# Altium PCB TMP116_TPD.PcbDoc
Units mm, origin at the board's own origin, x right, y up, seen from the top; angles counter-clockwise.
Board outline 10.92 x 3.99 mm, 2 copper layers (Top Layer, Bottom Layer), stack 0.605 mm thick; 19 components, 5 nets, 29 pads, 4 vias.
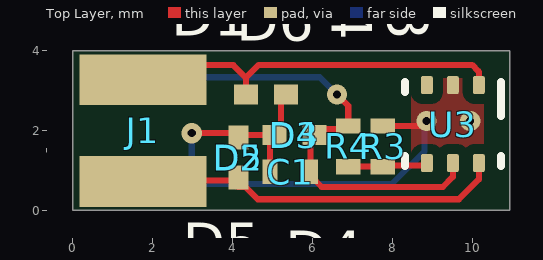
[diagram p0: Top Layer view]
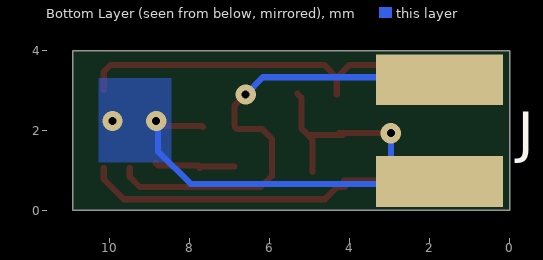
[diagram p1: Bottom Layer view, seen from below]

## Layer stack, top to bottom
Top Solder: solder mask 0.0102, Solder Resist, Dk 3.5
Top Layer: signal copper 0.0356
Dielectric1: core 0.5334, FR-4, Dk 4.2
Bottom Layer: signal copper 0.0356
Bottom Solder: solder mask 0.0102, Solder Resist, Dk 3.5

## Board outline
0,0 10.922,0 10.922,3.988 0,3.988

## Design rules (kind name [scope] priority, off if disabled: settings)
AcuteAngle [All] p1: minimum=4.50000000000000E+0001 checktracksonly=FALSE
AssemblyTestPointUsage [All] p1: valid=2
BoardOutlineClearance BoardOutlineClearance_MountingHoles [OnCopper and InComponentClass('Mounting Holes')] p1: gap=1.016 ignorepadtopadclearanceinfootprint=FALSE
BoardOutlineClearance BoardOutlineClearance_Poly [OnCopper and IsPoly] p2: gap=0.635 ignorepadtopadclearanceinfootprint=FALSE
BoardOutlineClearance [OnCopper and Not InComponentClass('Logo') and not InComponentClass('FiducialMark') and not InRegion(1000,500,4000,800) and not InPoly and not InComponent('J1','J2')] p3: gap=0.5 ignorepadtopadclearanceinfootprint=FALSE except(0.2: Track-OutlineEdge)
Clearance Clearance_2 [InNamedPolygon('BOTTOM_LAYER_GND_P002')] p1: gap=0.254 ignorepadtopadclearanceinfootprint=FALSE except(0: Arc-Hole Track-Hole SMDPad-Hole THPad-Hole Via-Via Via-Fill Via-Poly Via-Region Via-Text Via-Hole Fill-Hole Poly-Hole Region-Hole Text-Hole)
Clearance Clearance_1 [InNamedPolygon('TOP_LAYER_GND_P000')] p2: gap=0.254 ignorepadtopadclearanceinfootprint=FALSE except(0: Arc-Hole Track-Hole SMDPad-Hole THPad-Hole Via-Via Via-Fill Via-Poly Via-Region Via-Text Via-Hole Fill-Hole Poly-Hole Region-Hole Text-Hole)
Clearance Clearance_Keepouts [((IsTrack Or IsArc) And Not InPoly) And IsFree and IsKeepOut vs ((IsTrack Or IsArc) And Not InPoly) And IsFree and IsKeepOut] p3: gap=0 ignorepadtopadclearanceinfootprint=FALSE
Clearance Clearance_Poly [InPolygon] p4: gap=0.635 ignorepadtopadclearanceinfootprint=FALSE except(0: Arc-Hole Track-Hole SMDPad-Hole THPad-Hole Via-Hole Fill-Hole Poly-Hole Region-Hole Text-Hole)
Clearance Clearance_FiducialMark [IsKeepOut and InComponentClass('FiducialMark') vs IsPad and InComponentClass('FiducialMark')] p5: gap=0 ignorepadtopadclearanceinfootprint=FALSE
Clearance [All] p6: gap=0.2 ignorepadtopadclearanceinfootprint=FALSE except(0: Arc-Hole Track-Hole SMDPad-Hole THPad-Hole Via-Hole Fill-Hole Poly-Hole Region-Hole Text-Hole; 0.152: Arc-Arc Arc-Track Track-Track)
ComponentClearance ComponentClearance_AlternateParts [incomponent('D1') OR incomponent('D2') OR incomponent('D3') vs incomponent('U4') OR incomponent('U5') OR incomponent('U6')] p1: gap=0 collisioncheckmode=3 verticalgap=0 showdistances=FALSE
ComponentClearance ComponentClearance_MountingHoles_FiducialMarks [InComponentClass('Mounting Holes') vs InComponentClass('FiducialMark')] p2: gap=1.27 collisioncheckmode=3 verticalgap=0.254 showdistances=FALSE
ComponentClearance ComponentClearance_Shunt [InComponentClass('Header') vs InComponentClass('Shunt')] p3: gap=0 collisioncheckmode=3 verticalgap=0 showdistances=FALSE
ComponentClearance ComponentClearance_Logo [InComponentClass('Logo')] p4: gap=1.27 collisioncheckmode=3 verticalgap=0.254 showdistances=FALSE
ComponentClearance ComponentClearance_ScrewToNut [(HasFootprint('NY PMS 440 0025 PH')) vs (HasFootprint('Keystone_1902C'))] p5: gap=0.127 collisioncheckmode=3 verticalgap=0.254 showdistances=FALSE
ComponentClearance ComponentClearance_MountingHoles [InComponentClass('Mounting Holes')] p6: gap=6.35 collisioncheckmode=3 verticalgap=2540 showdistances=FALSE
ComponentClearance ComponentClearance_SmallPassives [HasFootprint('0201*') or HasFootprint('0402*') or HasFootprint('0508') or HasFootprint('0603*') or HasFootprint('0612') or HasFootprint('0805*') or HasFootprint('0815*') or HasFootprint('0830*') or HasFootprint('1206*') or HasFootprint('1210*') or HasFootprint('1808*') or HasFootprint('1812*') or HasFootprint('1825*') or HasFootprint('2010*') or HasFootprint('2220*') or HasFootprint('2225*') or HasFootprint('2512*') or HasFootprint('2728*') or HasFootprint('3518*') or HasFootprint('DPY0002A') vs HasFootprint('0201*') or HasFootprint('0402*') or HasFootprint('0508') or HasFootprint('0603*') or HasFootprint('0612') or HasFootprint('0805*') or HasFootprint('0815*') or HasFootprint('0830*') or HasFootprint('1206*') or HasFootprint('1210*') or HasFootprint('1808*') or HasFootprint('1812*') or HasFootprint('1825*') or HasFootprint('2010*') or HasFootprint('2220*') or HasFootprint('2225*') or HasFootprint('2512*') or HasFootprint('2728*') or HasFootprint('3518*') or HasFootprint('DPY0002A')] p7: gap=0.254 collisioncheckmode=3 verticalgap=0.254 showdistances=FALSE
ComponentClearance ComponentClearance_THtoSMT [IsThruComponent vs IsSMTComponent] p8: gap=1.016 collisioncheckmode=3 verticalgap=0.762 showdistances=FALSE
ComponentClearance ComponentClearance_THtoTH [IsThruComponent vs IsThruComponent] p9: gap=0.762 collisioncheckmode=3 verticalgap=0.762 showdistances=FALSE
ComponentClearance [All] p10: gap=0.381 collisioncheckmode=3 verticalgap=0.254 showdistances=FALSE
DiffPairsRouting [All] p1: maxlimit=2.54 minlimit=0.254 mostfreqgap=0.254 toplayer_minwidth=0.381 toplayer_maxwidth=0.381 toplayer_prefwidth=0.381 bottomlayer_minwidth=0.381 bottomlayer_maxwidth=0.381 bottomlayer_prefwidth=0.381 maxuncoupledlength=25.4
FabricationTestPointUsage TestPointUsage [All] p1: valid=2 allowmultiple=FALSE
FabricationTestpoint Testpoint [All] p1: side=3 testpointundercomponent=TRUE minsize=1.016 maxsize=2.54 preferedsize=1.524 minholesize=0 maxholesize=1.016 preferedholesize=0.813 testpointgrid=0.025 allowsidetop=TRUE allowsidebottom=TRUE usegrid=TRUE gridtolerance=0
FanoutControl Fanout_LCC [IsLCC] p1: bgadir=Out bgaviamode=Centered fanoutstyle=Auto fanoutdirection=Alternating viagrid=0.025 // Fanout_LCC (Default Rule)
FanoutControl Fanout_BGA [IsBGA] p2: bgadir=Out bgaviamode=Centered fanoutstyle=Auto fanoutdirection=Alternating viagrid=0.025 // Fanout_BGA (Default Rule)
FanoutControl Fanout_Default [All] p4: bgadir=Out bgaviamode=Centered fanoutstyle=Auto fanoutdirection=Alternating viagrid=0.025 // Fanout_Default (Default Rule)
FanoutControl Fanout_Small [(CompPinCount < 5)] p5: bgadir=Out bgaviamode=Centered fanoutstyle=Auto fanoutdirection=OutThenIn viagrid=0.025 // Fanout_Small (Default Rule)
HoleSize [All] p1: absolutevalues=TRUE maxlimit=6.375 minlimit=0.2 maxpercent=80.000 minpercent=20.000
MinimumAnnularRing MinimumAnnularRing_ThermalPadVias [IsVia and InAnyComponent] p1: minimumring=0.15
MinimumAnnularRing [All] p2: minimumring=0.152
MinimumSolderMaskSliver MinimumSolderMaskSliver_Logo [InComponentClass('Logo') vs InComponentClass('Logo')] p1: minsoldermaskwidth=0.018
MinimumSolderMaskSliver [All] p2: minsoldermaskwidth=0.1
PlaneConnect [All] p1: planeconnectstyle=Direct reliefexpansion=0.254 reliefentries=4 reliefconductorwidth=0.254 reliefairgap=0.254
PolygonConnect PolygonConnect_2 [All vs IsNamedPolygon('BOTTOM_LAYER_GND_P002')] p1: connectstyle=Direct reliefconductorwidth=0.254 reliefentries=4 polygonreliefangle="90 Angle" airgapwidth=0.254
PolygonConnect PolygonConnect_1 [All vs IsNamedPolygon('TOP_LAYER_GND_P000')] p2: connectstyle=Direct reliefconductorwidth=0.254 reliefentries=4 polygonreliefangle="90 Angle" airgapwidth=0.254
PolygonConnect [All] p3: thpad.connectstyle=Relief thpad.reliefconductorwidth=0.254 thpad.reliefentries=4 thpad.polygonreliefangle="90 Angle" thpad.airgapwidth=0.254 smdpad.connectstyle=Relief smdpad.reliefconductorwidth=0.254 smdpad.reliefentries=4 smdpad.polygonreliefangle="90 Angle" smdpad.airgapwidth=0.254 via.connectstyle=Direct via.reliefconductorwidth=0.254 via.reliefentries=4 via.polygonreliefangle="90 Angle" via.airgapwidth=0.254
RoutingVias ThermalPadVias [IsVia and InAnyComponent] p1: holewidth=0.2 width=0.5 viastyle="Through Hole" minholewidth=0.2 minwidth=0.5 maxholewidth=0.33 maxwidth=0.6
RoutingVias [All] p2: holewidth=0.406 width=0.864 viastyle="Through Hole" minholewidth=0.203 minwidth=0.508 maxholewidth=1.016 maxwidth=1.651
SilkToBoardRegionClearance [Not ((IsComment or IsDesignator) And (Hide <> 'False')) and not InRegion(1000,500,4000,800)] p1:
SilkToSilkClearance SilkToSilkClearance_Pb-FreeLogo [(HasFootprint('Pb-Free_Overlay_Medium') OR HasFootprint('Pb-Free_Overlay_Small')) vs (HasFootprint('Pb-Free_Overlay_Medium') OR HasFootprint('Pb-Free_Overlay_Small'))] p1: silktosilkclearance=0
SilkToSilkClearance [All] p2: silktosilkclearance=0.102
SilkToSolderMaskClearance SilkToComponentPadClearance [(IsPad or IsFill or IsRegion) and InAnycomponent] p1: minsilkscreentomaskgap=0.127 clearancetoexposedcopper=TRUE
SilkToSolderMaskClearance "Silk to Solder Mask Opening" [All] p2: minsilkscreentomaskgap=0.102 clearancetoexposedcopper=FALSE
SolderMaskExpansion [All] p1: expansion=0.05
Width [All] p1: maxlimit=2.54 minlimit=0.152 preferedwidth=0.254 checkconnectedcopper=TRUE
15 further rules are at their usual default settings.

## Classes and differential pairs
component class TMP116_TPD: C1 D1 D2 D3 D4 D5 D6 J1 J2 R3 R4 U3
component class EVM_Hardware: LBL1 Logo2 Logo3 ZZ1 ZZ2 ZZ3 ZZ4
component class AssemblyNote: ZZ1 ZZ2 ZZ3 ZZ4
component class Label: LBL1

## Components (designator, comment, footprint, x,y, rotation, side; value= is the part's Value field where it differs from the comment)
C1 "GCM155L81E104KE02J" 0402S 5.436,0.965 r180 top value=0.1uF
D1 "TPD1E04U04DPLR" DPY0002A 4.826,2.896 r0 top
D2 "TPD1E04U04DPLR" DPY0002A 4.14,1.321 r90 top
D3 "TPD1E04U04DPLR" DPY0002A 5.537,1.88 r180 top
D4 "ESD351DPYR" DPY0002A 5.537,1.88 r180 top
D5 "ESD351DPYR" DPY0002A 4.14,1.321 r90 top
D6 "ESD351DPYR" DPY0002A 4.826,2.896 r0 top
J1 "TSM-102-01-L-SH" Samtec_TSM-102-01-x-SH -3.527,1.994 r270 top
J2 "TSM-102-01-L-SH" Samtec_TSM-102-01-x-SH -3.527,1.994 r90 bottom
LBL1 "THT-14-423-10" Label_650x200 17.272,17.932 r0 top
Logo2 "Pb-Free Symbol" Pb-Free_Overlay_Small 5.817,14.656 r0 top
Logo3 "FCC disclaimer" FCC_disclaimer 8.357,23.622 r0 top
R3 "CRCW04020000Z0ED" 0402S 7.747,1.6 r90 top value=0
R4 "CRCW04020000Z0ED" 0402S 6.883,1.6 r90 top value=0
U3 "TMP116MAIDRVR" DRV0006B 9.5,2.159 r270 top
ZZ1 "This Assembly Note is for PCB labels only" AssemblyNoteLabel 3.759,35.839 r0 top
ZZ2 "These assemblies are ESD sensitive, ESD precautions shall be observed." AssemblyNote 3.759,33.074 r0 top
ZZ3 "These assemblies must be clean and free from flux and all contaminants. Use of no clean flux is not acceptable." AssemblyNote 3.759,30.824 r0 top
ZZ4 "These assemblies must comply with workmanship standards IPC-A-610 Class 2, unless otherwise specified." AssemblyNote 3.759,28.575 r0 top

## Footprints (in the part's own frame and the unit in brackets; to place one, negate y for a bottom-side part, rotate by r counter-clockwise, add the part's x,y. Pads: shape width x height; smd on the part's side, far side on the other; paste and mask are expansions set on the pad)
0402S [mil] "Based on C0402S footprint from PADS legacy"
  rect 15x24 smd: 1(-20,0) 2(20,0)
  body extent -22,-12 22,12, height 24
AssemblyNote [mm] "Assembly Note"
AssemblyNoteLabel [mm] "Assembly Note for PCB Labels"
DPY0002A [mm] "R-PX2SON-N2"
  rect 0.6x0.5 smd: 1(-0.5,0) 2(0.5,0)
  body extent -0.55,-0.35 0.55,0.35, height 0.4
DRV0006B [mm] "SON, 6-Leads, Body 2x2mm, Pitch 0.65mm, TI Recommended"
  rrect33% 0.45x0.3 smd: 1(-0.975,0.65) 2(-0.975,0) 3(-0.975,-0.65) 4(0.975,-0.65) 5(0.975,0) 6(0.975,0.65)
  silkscreen extent -1.05,-1.2 1.05,1.2, body extent -1.05,-1.05 1.05,1.05, height 0.81
FCC_disclaimer [mm]
Label_650x200 [mil] "Thermal Transfer Label"
  round 1 on Mech13: 0(0,0)
  silkscreen extent -325,-100 325,100, body extent -325,-100 325,100, height 1
Pb-Free_Overlay_Small [mm]
  silkscreen extent -1.16,-1.17 1.17,1.17
Samtec_TSM-102-01-x-SH [mm] "Header, 2.54mm, 2x1, R/A, SMT"
  rect 1.27x3.18 smd: 1(-1.27,5.28) 2(1.27,5.28)
  silkscreen extent -2.9,-1.27 2.54,1.27, body extent -2.54,-7.11 2.54,5.84, height 3.05

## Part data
C1: "CAP, CERM, 0.1 µF, 50 V,+/- 10%, X8L, 0402", Cap_Case=0402, Manufacturer=MuRata, TempCo=X8L, Tolerance_%=10, Value2=50V, ValueDisplayed=0.1µF
D1 D2 D3: library part TPD1E0xU0x, "1-Channel ESD Protection Diode With Low Dynamic Resistance for HDMI 2.0 and USB 3.0, DPL0002A (X2SON-2)", Alternate Manufacturer="Texas Instruments", Alternate PartNumber=TPD1E04U04DPLT
D4 D5 D6: library part CMP-0084110-1, "1-Channel 30 kV ESD Protection Diode With Low Clamping Voltage in 0402 Package, DPY0002A (X1SON-2)", Alternate Manufacturer="Texas Instruments", Operating Temperature Range="-40 to 125 C", Rating=Catalog
J1 J2: "Header, 2.54mm, 2x1, Gold with Tin Tail, R/A, SMT", Color=Black, Current_A=5.4, Manufacturer=Samtec, Supplier Part Number 1=TSM-102-01-L-SH-ND, Voltage_V=475
LBL1: library part CMP-0003625-1, "Thermal Transfer Printable Labels, 0.650\" W x 0.200\" H - 10,000 per roll", Manufacturer=Brady, Supplier Part Number 1=97C5133
Logo2: library part CMP-0074839-1
Logo3: library part CMP-0074847-1, "FCC_disclaimer"
R3 R4: "RES, 0, 5%, 0.063 W, 0402", Manufacturer=Vishay-Dale, Power_W=0.063, Supplier Part Number 1=541-0.0JCT-ND, TempCo="200 ppm/C", Tolerance_%=5, Value1=5%, Value2=0.063W, Value_Code=0000, ValueDisplayed=0
U3: library part CMP-0077792-1, "High-Accuracy, Low-Power, Digital Temperature Sensor With SMBus- and I2C-Compatible Interface, DRV0006B (WSON-6)", Alternate Manufacturer="Texas Instruments", Alternate PartNumber=TMP116MAIDRVT
ZZ1: library part CMP-0003616-3
ZZ2: library part CMP-0077236-1
ZZ3: library part CMP-0077237-1
ZZ4: library part CMP-0077238-1

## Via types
v1: diameter 0.508, hole 0.203, Top Layer to Bottom Layer, tented both sides, 4 vias

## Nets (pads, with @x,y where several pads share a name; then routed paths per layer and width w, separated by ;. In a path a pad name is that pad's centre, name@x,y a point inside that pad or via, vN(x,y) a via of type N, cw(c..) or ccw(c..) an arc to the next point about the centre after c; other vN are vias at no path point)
ADD0: R3.1 R4.1 U3.4 | length 2
  Top Layer w0.152: R4.1 R3.1 7.777,1.122 8.788,1.122 U3.4 ; R3.1@7.747,1.067 R3.1@7.757,1.057
GND: C1.2 D1.2 D2.2 D3.2 D4.2 D5.2 D6.2 J2.1 R3.2 U3.2 | length 15.5
  Top Layer w0.152: v1(2.972,1.93) D5.2@4.267,1.93 ; D5.2@4.166,1.88 D4.2 ; C1.2 4.928,1.77 D4.2 ; D6.2@5.309,2.921 5.207,2.819 5.207,2.049 D4.2 ; R3.2@7.671,2.083 7.696,2.108 8.712,2.108 v1(8.839,2.235)
  Bottom Layer w0.152: J2.1@1.749,0.66 7.978,0.66 8.789,1.471 8.789,2.064 v1@8.89,2.165 ; J2.1@2.035,0.946 2.851,0.946 2.972,1.067 v1(2.972,1.93)
  other v1: 9.931,2.235
SCL: D1.1 D6.1 J1.1 U3.1 | length 8.7
  Top Layer w0.152: J1.1@1.749,3.486 J1.1@1.749,3.651 ; J1.1@2.616,3.226 J1.1@2.845,3.454 ; J1.1@3.124,3.632 4.013,3.632 4.326,3.319 ; D6.1 4.326,3.319 ; 10.134,3.479 10.15,3.463 U3.1 U3.1@10.15,3.007 ; 10.135,3.48 9.979,3.635 4.642,3.635 4.326,3.319
SDA: D2.1 D5.1 J1.2 U3.6 | length 9.5
  Top Layer w0.152: J1.2@2.023,0.413 1.749,0.686 1.808,0.745 D5.1@4.14,0.745 ; D5.1@4.115,0.59 4.312,0.59 4.623,0.279 9.65,0.279 10.15,0.779 U3.6@10.15,1.057
V+: C1.1 D3.1 D4.1 J2.2 R4.2 U3.5 | length 12
  Top Layer w0.152: D4.1@6.034,1.88 D4.1@6.034,1.877 ; v1(6.604,2.896) 6.883,2.616 R4.2 6.807,2.032 6.19,2.032 D4.1 D4.1@6.034,1.877 ; U3.5@9.5,1.057 9.5,0.836 9.248,0.584 6.223,0.584 5.944,0.864 C1.1 5.944,1.786 D4.1@6.034,1.877
  Bottom Layer w0.152: J2.2@1.749,3.2 1.876,3.327 6.172,3.327 v1(6.604,2.896)
pads on no net: LBL1.0 U3.3

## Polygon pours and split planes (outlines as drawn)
GND on Bottom Layer "BOTTOM_LAYER_GND_P002" (solid, pour order 2): 8.458,3.303 8.458,1.203 10.363,1.203 10.325,3.303
GND on Top Layer "TOP_LAYER_GND_P000" (solid, pour order 0): 8.458,3.317 8.458,1.217 10.524,1.217 10.524,3.317

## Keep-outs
Keep-Out Layer:
  text ".Layer_Name" at 14.656,-21.806 h1.52

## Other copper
Top Layer:
  text ".Layer_Name" at 14.656,-21.806 h1.52
Bottom Layer:
  text ".Layer_Name" at 14.656,-21.806 h1.52

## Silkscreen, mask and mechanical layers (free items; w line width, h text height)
Top Overlay:
  region: 18.415,13.36 10.795,13.36 10.795,10.82 18.415,10.82
  text ".PRJ_Number" at 3.48,11.786 h1.02
  text ".PCB_Rev" at 9.271,11.735 h1.02
  text ".Layer_Name" at 14.656,-21.806 h1.52
Bottom Overlay:
  text ".Layer_Name" at 14.656,-21.806 h1.52
Top Paste:
  text ".Layer_Name" at 14.656,-21.806 h1.52
Bottom Paste:
  text ".Layer_Name" at 14.656,-21.806 h1.52
Top Solder:
  text ".Layer_Name" at 14.656,-21.806 h1.52
  text ".Layer_Name" at 14.656,-21.806 h1.52
Bottom Solder:
  text ".Layer_Name" at 14.656,-21.806 h1.52
Drill Guide:
  text ".Layer_Name" at 14.656,-21.806 h1.52
M1 Board Outline:
  the board outline again, w0.254
  text ".Layer_Name" at 14.656,-21.806 h1.52
M2 Board Dimensions:
  rectangle: 0,-6.985 3.175,-3.81
  rectangle: 3.175,-10.16 12.7,-6.985
  lines w0.178: 0,-6.985 25.4,-6.985 ; 3.175,-10.16 3.175,-3.81 ; 6.35,-10.16 6.35,-3.81 ; 12.7,-10.16 12.7,-3.81 ; 19.05,-10.16 19.05,-3.81 ; 0,-10.16 25.4,-10.16 25.4,-3.81 0,-3.81 0,-10.16
  text ".Layer_Name" at 14.656,-21.806 h1.52
M3 3D STEP Top:
  text ".Layer_Name" at 14.656,-21.806 h1.52
M4 3D STEP Bottom:
  text ".Layer_Name" at 14.656,-21.806 h1.52
M5 Assembly Top:
  lines w0.254: -7.417,-23.626 160.223,-23.626 ; -7.417,-18.462 160.274,-18.462 ; -7.417,-13.297 -7.417,-28.791 94.31,-28.791 160.274,-28.791 160.274,-13.297 -7.404,-13.297 -7.404,-28.791 32.614,-28.791 ; 55.194,-28.791 55.194,-13.297 ; 87.376,-18.462 87.376,-13.297 ; 108.712,-18.462 108.712,-13.297 ; 124.511,-28.956 124.511,-23.804
  text "COMPONENTS MARKED 'DNP' SHOULD NOT BE POPULATED." at 29.299,-8.09 h1.52
  text "ASSEMBLY VARIANT:" at 29.286,-11.024 h1.52
  text ".VariantName" at 55.601,-11.024 h1.52
  text "PCB VIEWED FROM TOP SIDE" at -5.804,-16.654 h1.52
  text "BOARD #:" at 57.099,-16.654 h1.52
  text ".PRJ_Number" at 70.955,-16.654 h1.52
  text "REV:" at 92.405,-16.654 h1.52
  text ".PCB_Rev" at 99.809,-16.654 h1.52
  text "SVN REV:" at 113.69,-16.654 h1.52
  text ".VersionControl_RevNumber" at 126.543,-16.654 h1.52
  text "TID #:" at 57.099,-21.819 h1.52
  text ".TID" at 70.955,-21.819 h1.52
  text "PLOT NAME =" at -5.804,-27.034 h1.52
  text ".plot_File_Name" at 14.656,-27.034 h1.52
  text "GENERATED    :" at 57.15,-27.034 h1.52
  text ".Print_Date" at 79.235,-27.034 h1.52
  text ".Print_Time" at 97.752,-27.034 h1.52
  text "TEXAS INSTRUMENTS" at 129.87,-27.034 h1.52
M6 Assembly Bottom:
  lines w0.254: -7.429,-18.474 160.261,-18.474 ; -7.379,-23.639 160.261,-23.639 ; 28.334,-28.969 28.334,-23.817 ; 44.133,-18.474 44.133,-13.31 ; 65.468,-18.474 65.468,-13.31 ; 97.65,-28.804 97.65,-13.31 ; 120.231,-28.804 160.249,-28.804 160.249,-13.31 -7.429,-13.31 -7.429,-28.804 58.534,-28.804 160.261,-28.804 160.261,-13.31
  text "COMPONENTS MARKED 'DNP' SHOULD NOT BE POPULATED." at 154.991,-8.077 h1.52
  text ".VariantName" at 128.473,-11.024 h1.52
  text "ASSEMBLY VARIANT:" at 154.864,-11.024 h1.52
  text ".VersionControl_RevNumber" at 26.302,-16.667 h1.52
  text "SVN REV:" at 39.154,-16.667 h1.52
  text ".PCB_Rev" at 53.035,-16.667 h1.52
  text "REV:" at 60.439,-16.667 h1.52
  text ".PRJ_Number" at 81.89,-16.667 h1.52
  text "BOARD #:" at 95.745,-16.667 h1.52
  text "PCB VIEWED FROM BOTTOM SIDE" at 158.648,-16.667 h1.52
  text ".TID" at 81.89,-21.831 h1.52
  text "TID #:" at 95.745,-21.831 h1.52
  text "TEXAS INSTRUMENTS" at 22.974,-27.047 h1.52
  text ".Print_Time" at 55.093,-27.047 h1.52
  text ".Print_Date" at 73.609,-27.047 h1.52
  text "GENERATED    :" at 95.694,-27.047 h1.52
  text ".plot_File_Name" at 138.189,-27.047 h1.52
  text "PLOT NAME =" at 158.648,-27.047 h1.52
M9 Title Sheet:
  drawing of 57 lines, arcs and shapes, not listed
  text "1" at 18.792,204.127 h1.78
  text "2" at 82.182,204.127 h1.78
  text "3" at 145.411,204.127 h1.78
  text "4" at 209.08,204.127 h1.78
  text "5" at 272.555,204.127 h1.78
  text "6" at 336.182,204.127 h1.78
  text "A" at -10.579,175.095 h1.78
  text "A" at 365.341,175.095 h1.78
  text "B" at -10.579,114.643 h1.78
  text "B" at 365.341,114.643 h1.78
  text "C" at -10.579,54.318 h1.78
  text "C" at 365.341,54.318 h1.78
  text "PROJECT TITLE:" at 288.125,7.048 h1.14
  text ".PRJ_Title" at 289.395,3.662 h1.78
  text "DESIGNED FOR:" at 288.125,-0.597 h1.14
  text ".PRJ_Customer" at 289.395,-4.153 h1.78
  text "D" at -10.579,-5.88 h1.78
  text "D" at 365.341,-5.88 h1.78
  text "FILE NAME:" at 288.125,-8.217 h1.14
  text ".PCB_File_Name_No_Path" at 289.395,-11.265 h1.78
  text "Texas Instruments (TI) and/or its licensors do not warrant the accuracy or completeness of this specification" at 161.9,-15.376 h1.14
  text "ENGINEER:" at 288.125,-15.583 h1.14
  text "LAYOUT BY:" at 326.352,-15.583 h1.14
  text "or any information contained therein. TI and/or its licensors do not warrant that this design will meet" at 160.757,-18.237 h1.14
  text ".PRJ_Engineer" at 289.395,-19.52 h1.78
  text ".PCB_Layout" at 327.635,-19.52 h1.78
  text "the specifications, will be suitable for your application or fit for any particular purpose, or will operate in" at 160.757,-21.099 h1.14
  text ".Layer_Name" at 14.656,-21.806 h1.52
  text "ALTIUM DESIGNER VERSION:" at 326.352,-23.457 h1.14
  text "an implementation. TI and/or its licensors do not warrant that the design is production worthy. You should" at 160.757,-23.961 h1.14
  text "completely validate and test your design implementation to confirm the system functionality for your application." at 161.9,-26.822 h1.14
  text ".print_Scale" at 289.395,-26.843 h1.78
  text ".Application_BuildNumber" at 327.635,-26.843 h1.78
  text "1" at 18.792,-32.093 h1.78
  text "2" at 82.182,-32.093 h1.78
  text "3" at 145.411,-32.093 h1.78
  text "4" at 209.08,-32.093 h1.78
  text "5" at 272.555,-32.093 h1.78
  text "6" at 336.182,-32.093 h1.78
M10 Fab Notes:
  drawing of 189 lines, arcs and shapes, not listed
  text "DESIGN INFORMATION" at 314.503,161.447 h1.52
  text "MIN. TRACK WIDTH:" at 298.131,158.091 h1.52
  text "6" at 325.976,158.091 h1.52
  text "MIL" at 329.907,158.091 h1.52
  text "MIN. CLEARANCE:" at 298.131,154.938 h1.52
  text "0.15" at 324.452,154.938 h1.52
  text "mm" at 329.907,154.938 h1.52
  text "MIN. VIA PAD SIZE:" at 298.131,151.785 h1.52
  text "20" at 325.214,151.785 h1.52
  text "MIL" at 329.907,151.785 h1.52
  text "0.05mm (2MIL)" at 315.784,148.486 h1.52
  text "MINIMUM ANNULAR RING" at 289.769,148.277 h1.52
  text "EXTERNAL" at 333.768,148.277 h1.52
  text "PER" at 294.849,145.48 h1.52
  text "IPC-D-275 CLASS 2 LEVEL C" at 300.437,145.48 h1.52
  text "MIL, HOLES" at 338.238,142.928 h1.52
  text "+/-" at 328.27,142.709 h1.52
  text "+/-" at 349.961,142.709 h1.52
  text "REGISTRATION TOLERANCES:" at 289.769,142.682 h1.52
  text "METAL" at 320.243,142.682 h1.52
  text "5" at 334.879,142.683 h1.52
  text "3" at 356.037,142.683 h1.52
  text "MIL" at 358.99,142.682 h1.52
  text "HOLE SIZE TOLERANCE (UNLESS OTHERWISE SPECIFIED):" at 289.769,140.185 h1.52
  text "+/-" at 349.961,140.112 h1.52
  text "3" at 356.037,140.085 h1.52
  text "MIL" at 358.99,140.085 h1.52
  text "MATERIAL:" at 287.87,136.589 h1.52
  text "FR-4 High Tg" at 312.926,133.324 h1.52
  text "X" at 309.257,133.122 h1.52
  text "FR-408" at 298.563,133.007 h1.52
  text "OTHER" at 336.358,133.007 h1.52
  text "62 MIL (1.6mm) +/-10%" at 306.694,129.374 h1.52
  text "X" at 336.271,129.337 h1.52
  text "THICKNESS:" at 289.769,129.165 h1.52
  text "OTHER" at 339.33,129.165 h1.52
  text "0.5mm+/-10%" at 346.583,129.108 h1.52
  text "TOLERANCE:" at 289.769,125.652 h1.52
  text "X" at 311.314,125.652 h1.52
  text "ANSI IPC-6012 TYPE 3 CLASS 2" at 315.836,125.652 h1.52
  text "OTHER +/-" at 315.835,121.989 h1.52
  text "BOW & TWIST:" at 289.769,118.302 h1.52
  text "X" at 311.314,118.302 h1.52
  text "ANSI IPC-6012 TYPE 3 CLASS 2" at 315.836,118.302 h1.52
  text "OTHER +/-" at 315.835,114.576 h1.52
  text "DRILLING:" at 287.87,111.258 h1.52
  text "NC_DRILL FILES" at 332.599,108.586 h1.52
  text "REFERENCE:" at 289.769,108.486 h1.52
  text "X" at 306.463,108.484 h1.52
  text "AS SHOWN" at 310.984,108.486 h1.52
  text "X" at 329.348,108.486 h1.52
  text "OTHER" at 340.168,104.873 h1.52
  text "PTH COPPER THICKNESS:" at 289.761,104.783 h1.52
  text "X" at 318.697,104.783 h1.52
  text "20-30 um" at 321.948,104.783 h1.52
  text "BOARD FINISH:" at 287.87,101.034 h1.52
  text "SILKSCREEN:" at 291.812,98.237 h1.52
  text "TOP" at 319.112,98.237 h1.52
  text "BOTTOM" at 332.091,98.237 h1.52
  text "SILKSCREEN COLOR:" at 291.812,94.295 h1.52
  text "WHITE" at 319.112,94.295 h1.52
  text "OTHER" at 332.091,94.295 h1.52
  text "X" at 319.442,90.652 h1.52
  text "GREEN" at 322.439,90.652 h1.52
  text "OTHER" at 338.136,90.652 h1.52
  text "SOLDER RESIST COLOR:" at 291.812,90.477 h1.52
  text "X" at 319.442,86.734 h1.52
  text "MATTE" at 322.439,86.734 h1.52
  text "SEMI-GLOSS" at 338.125,86.717 h1.52
  text "IMMERSION GOLD (ENIG)" at 314.819,82.345 h1.52
  text "ENEPIG" at 348.793,82.162 h1.52
  text "SURFACE FINISH:" at 287.87,82.136 h1.52
  text "X" at 310.298,82.136 h1.52
  text "IMM. TIN/SILVER OR EQUIV" at 296.24,78.649 h1.52
  text "OTHER" at 332.599,78.549 h1.52
  text "ARRAY/PANEL:" at 287.87,74.602 h1.52
  text "CUT AND TRIM PER M1 BOARD OUTLINE" at 314.819,74.393 h1.52
  text "N.C. ROUTE" at 314.819,70.94 h1.52
  text "X" at 332.295,70.94 h1.52
  text "V. SCORE" at 336.816,70.94 h1.52
  text "CERTIFICATION:" at 287.87,67.66 h1.52
  text "MATERIALS AND WORKMANSHIP FOR ALL PCBS" at 306.285,67.66 h1.52
  text "TO MEET OR EXCEED THE REQUIREMENTS OF:" at 306.285,65.271 h1.52
  text "X" at 297.078,62.003 h1.52
  text "ANSI IPC-A-600F CLASS ->" at 300.329,62.003 h1.52
  text "X" at 342.188,62.003 h1.52
  text "2" at 344.982,62.003 h1.52
  text "1" at 336.981,61.965 h1.52
  text "3" at 353.973,61.965 h1.52
  text "X" at 317.702,58.252 h1.52
  text "RoHS" at 320.953,58.252 h1.52
  text "OTHER" at 337.321,58.252 h1.52
  text "PER ORDER" at 347.407,58.252 h1.52
  text "ALL BOARDS MUST MEET OR EXCEED UL94-V0 REQUIREMENTS." at 288.569,54.345 h1.52
  text "PCB MUST BEAR THE UL94V-0 UL REGISTERED MATERIAL ID NUMBER" at 288.569,51.397 h1.52
  text "ADDITIONAL REQUIREMENTS:" at 287.87,47.094 h1.52
  text "MICROSECTION:" at 289.769,44.373 h1.52
  text "YES" at 312.775,44.373 h1.52
  text "REQUIRED" at 334.657,40.707 h1.52
  text "BARE BOARD ELEC. TEST:" at 289.769,40.634 h1.52
  text "NONE" at 322.935,40.634 h1.52
  text "X" at 331.66,40.634 h1.52
  text "PER ORDER" at 349.693,40.634 h1.52
  text "XX MIL VIAS REQUIRE NON-CONDUCTIVE FILL AND PLANARIZE" at 294.04,35.428 h1.5
  text "XX MIL VIAS REQUIRE CONDUCTIVE FILL AND PLANARIZE" at 294.243,32.787 h1.52
  text "OUTER XX MIL VIAS REQUIRE 50 OHM SINGLE-ENDED IMPEDANCE" at 294.218,28.637 h1.47
  text "LAYER 2 & 3 (INNER LAYERS) XX MIL WIDE, XX MIL SPACE / TRACES REQUIRE 100 OHM DIFFERENTIAL IMPEDANCE" at 294.015,22.65 h1.52
  text ".Layer_Name" at 14.656,-21.806 h1.52
M11 Gerber Information:
  lines w0.254: -7.417,-23.626 160.223,-23.626 ; -7.417,-18.462 160.274,-18.462 ; -7.417,-13.297 -7.417,-28.791 94.31,-28.791 160.274,-28.791 160.274,-13.297 -7.404,-13.297 -7.404,-28.791 32.614,-28.791 ; 55.194,-28.791 55.194,-13.297 ; 87.376,-18.462 87.376,-13.297 ; 108.712,-18.462 108.712,-13.297 ; 124.511,-28.956 124.511,-23.804
  text "ALL ARTWORK VIEWED FROM TOP SIDE" at -5.804,-16.654 h1.52
  text "BOARD #:" at 57.099,-16.654 h1.52
  text ".PRJ_Number" at 70.955,-16.654 h1.52
  text "REV:" at 92.405,-16.654 h1.52
  text ".PCB_Rev" at 99.809,-16.654 h1.52
  text "SVN REV:" at 113.69,-16.654 h1.52
  text ".VersionControl_RevNumber" at 126.543,-16.654 h1.52
  text "LAYER NAME =" at -5.804,-21.806 h1.52
  text "TID #:" at 57.099,-21.819 h1.52
  text ".TID" at 70.955,-21.819 h1.52
  text "PLOT NAME =" at -5.804,-27.034 h1.52
  text ".plot_File_Name" at 14.656,-27.034 h1.52
  text "GENERATED    :" at 57.15,-27.034 h1.52
  text ".Print_Date" at 79.235,-27.034 h1.52
  text ".Print_Time" at 97.752,-27.034 h1.52
  text "TEXAS INSTRUMENTS" at 129.87,-27.034 h1.52
M12 Stackup:
  drawing of 191 lines, arcs and shapes, not listed
  text "Layer" at 249.331,199.644 h1.52
  text "Name" at 259.743,199.644 h1.52
  text "Material" at 283.359,199.644 h1.52
  text "Thickness" at 305.197,199.644 h1.52
  text "Constant" at 321.703,199.644 h1.52
  text "Board Layer Stack" at 336.177,199.644 h1.52
  text "1" at 249.331,196.596 h1.52
  text "Top Overlay" at 259.743,196.596 h1.52
  text "2" at 249.331,193.548 h1.52
  text "Top Solder" at 259.743,193.548 h1.52
  text "Solder Resist" at 283.359,193.548 h1.52
  text "0.40mil" at 305.197,193.548 h1.52
  text "3.5" at 321.703,193.548 h1.52
  text "3" at 249.331,190.5 h1.52
  text "Top Layer" at 259.743,190.5 h1.52
  text "Copper" at 283.359,190.5 h1.52
  text "1.40mil" at 305.197,190.5 h1.52
  text "4" at 249.331,187.452 h1.52
  text "Dielectric1" at 259.743,187.452 h1.52
  text "FR-4" at 283.359,187.452 h1.52
  text "21.00mil" at 305.197,187.452 h1.52
  text "4.2" at 321.703,187.452 h1.52
  text "5" at 249.331,184.404 h1.52
  text "Bottom Layer" at 259.743,184.404 h1.52
  text "Copper" at 283.359,184.404 h1.52
  text "1.40mil" at 305.197,184.404 h1.52
  text "6" at 249.331,181.356 h1.52
  text "Bottom Solder" at 259.743,181.356 h1.52
  text "Solder Resist" at 283.359,181.356 h1.52
  text "0.40mil" at 305.197,181.356 h1.52
  text "3.5" at 321.703,181.356 h1.52
  text "7" at 249.331,178.308 h1.52
  text "Bottom Overlay" at 259.743,178.308 h1.52
  text ".Layer_Name" at 14.656,-21.806 h1.52
M13 Component Bodies Top:
  text ".Layer_Name" at 14.656,-21.806 h1.52
M14 Component Bodies Bottom:
  text ".Layer_Name" at 14.656,-21.806 h1.52
M15 Courtyards Top:
  text ".Layer_Name" at 14.656,-21.806 h1.52
M16 Courtyards Bottom:
  text ".Layer_Name" at 14.656,-21.806 h1.52
Drill Drawing:
  circle w0.254: c27.933,4.679 r0.561
  lines w0.305: 26.34,3.362 74.306,3.362 ; 26.34,5.885 74.306,5.885 ; 34.353,0.839 34.353,8.407 ; 42.407,0.839 42.407,8.407 ; 58.197,0.839 58.197,8.407 ; 64.4,0.839 64.4,8.407 ; 26.34,0.839 74.306,0.839 74.306,8.407 26.34,8.407 26.34,0.839
  text "Symbol" at 27.853,6.641 h1.83
  text "Quantity" at 35.11,6.641 h1.83
  text "Finished Hole Size" at 43.164,6.641 h1.83
  text "Plated" at 58.954,6.641 h1.83
  text "Hole Type" at 65.156,6.641 h1.83
  text "4" at 35.11,4.119 h1.52
  text "0.203mm (8.00mil)" at 43.164,4.119 h1.52
  text "PTH" at 58.954,4.119 h1.52
  text "Round" at 65.156,4.119 h1.52
  text "4 Total" at 35.11,1.596 h1.52
  text ".Layer_Name" at 14.656,-21.806 h1.52
M17 Embedded Cavity:
  text ".Layer_Name" at 14.656,-21.806 h1.52
M18 Embedded Assembly:
  text ".Layer_Name" at 14.656,-21.806 h1.52
M19 Embedded Keepout:
  text ".Layer_Name" at 14.656,-21.806 h1.52

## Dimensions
0,0 to 10.922,0 on M2 Board Dimensions
0,0 to 0,3.988 on M2 Board Dimensions
0,-10.16 to 25.4,-10.16 on M2 Board Dimensions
